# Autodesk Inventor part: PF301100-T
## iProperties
Created: 2006-03
Part Number: PF301100-T
Material: 1.0037 St 37-2
Document SubType Name: Modellieren
Designer: TMT
Manufacturer: Standard
Standards Organization: Custom
Description: Pratze (ST.-verz.) DN 63-100 ISO
Vendor: PFEIFFER
Author: TMT
Comments: PFEIFER
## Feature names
1. Extrusion2
2. Extrusion3
3. Extrusion4
4. Extrusion5
5. Extrusion6
6. Extrusion7
7. Rundung3 [Fillet]
8. Rundung4 [Fillet]
9. Extrusion8
